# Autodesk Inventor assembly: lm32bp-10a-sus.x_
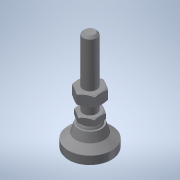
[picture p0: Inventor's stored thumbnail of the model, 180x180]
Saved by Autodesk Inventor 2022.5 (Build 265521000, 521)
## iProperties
Part Number: lm32bp-10a-sus.x_
Material: 一般
Document SubType Name: Assembly
Designer: ImaoCorp
Sending System: SOLIDWORKS 2017-2017317
MC: AMD64
MC_MODEL: Intel64 Family 6 Model 60 Stepping 3, GenuineIntel
OS: Windows_NT
FRU: Parasolid Version 29.0, build 201,  4-17-2017
FORMAT: text
GUISE: transmit
KEY: lm32bp-10a-sus
FILE: lm32bp-10a-sus.x_t
DATE: Mon Jul 01 17:50:50 2019
Author: ImaoCorp
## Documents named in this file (3)
- X:\14_SW2022-Inv2022\00_全2023-1023新製品(TCC)まで\l\lm32bp-10a-sus\LM32BP-10A-SUS.iam
- X:\14_SW2022-Inv2022\00_全2023-1023新製品(TCC)まで\l\lm32bp-10a-sus\lm32bp-10a-sus_01.ipt
- X:\14_SW2022-Inv2022\00_全2023-1023新製品(TCC)まで\l\lm32bp-10a-sus\lm32bp-10a-sus_02.ipt
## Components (2 placed, 2 different names)
1. lm32bp-10a-sus_01
2. lm32bp-10a-sus_02
